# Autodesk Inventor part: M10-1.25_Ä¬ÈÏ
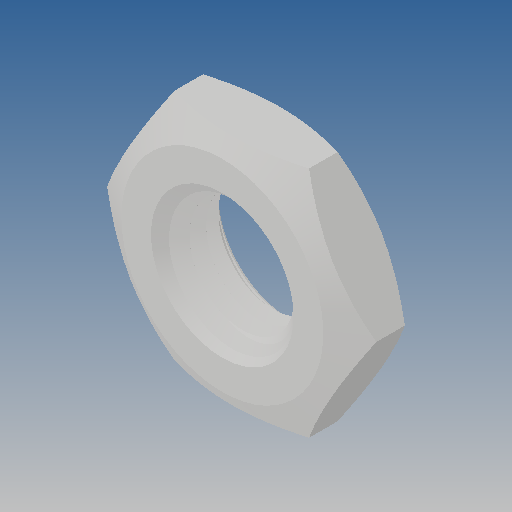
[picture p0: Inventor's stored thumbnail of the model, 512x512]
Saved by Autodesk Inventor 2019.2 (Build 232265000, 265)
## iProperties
Created: 2010-06
Part Number: M10-1.25_Ä¬ÈÏ
Material: Ogólny
Document SubType Name: Modeling
Designer: CADENGINEERING4
Density: 1 g/cm^3
Appearance: Domyślna
Author: CADENGINEERING4
Revision Number: ÈÎºÎ
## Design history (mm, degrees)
feature "NONE"
node "Bryła1"
